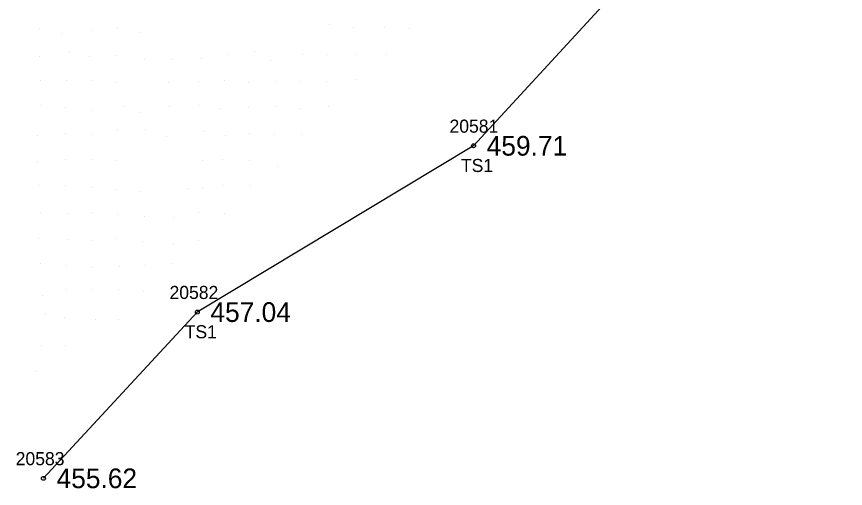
# Model space of a CAD drawing. Extents: x 1747760 to 1751131, y 649333 to 653784.
# Drawn here: x 1749176.7 to 1749239.9, y 651202.6 to 651238.6 of the extents above; entities that cross this region are included whole.
import ezdxf

# ---------------------------------------------------------------- set-up
doc = ezdxf.new("R2010")
doc.units = 0
for name, color, linetype in [('RD_DTM_BkLn2', 7, 'Continuous'), ('RD_DTM_BkLn_txCode', 7, 'Continuous'), ('RD_DTM_Spot', 7, 'Continuous'), ('RD_EX_TX_Misc_ELEV', 7, 'Continuous'), ('RD_SMD_Locator', 7, 'Continuous')]:
    doc.layers.add(name, color=color, linetype=linetype)

msp = doc.modelspace()

# ---------------------------------------------------------------- linework, layer by layer
at = {"layer": 'RD_DTM_BkLn2'}
msp.add_lwpolyline([(1749334.274, 651347.939), (1749311.737, 651326.42), (1749292.613, 651306.019), (1749271.131, 651290.935), (1749254.537, 651276.811), (1749242.73, 651265.483), (1749232.71, 651251.743), (1749211.561, 651228.743), (1749190.496, 651216.053), (1749178.766, 651203.369)], dxfattribs=at)
at = {"layer": 'RD_DTM_Spot'}
for p, q in [((1749178.471, 651237.712), (1749178.471, 651237.712)), ((1749182.48, 651237.556), (1749182.48, 651237.556)), ((1749184.386, 651237.715), (1749184.386, 651237.715)), ((1749200.569, 651237.99), (1749200.569, 651237.99)), ((1749202.383, 651237.788), (1749202.383, 651237.788)), ((1749204.76, 651237.744), (1749204.76, 651237.744)), ((1749206.691, 651237.729), (1749206.691, 651237.729)), ((1749180.152, 651237.316), (1749180.152, 651237.316)), ((1749186.198, 651237.38), (1749186.198, 651237.38)), ((1749178.46, 651235.542), (1749178.46, 651235.542)), ((1749180.761, 651235.896), (1749180.761, 651235.896)), ((1749182.305, 651235.564), (1749182.305, 651235.564)), ((1749184.269, 651235.663), (1749184.269, 651235.663)), ((1749192.763, 651235.694), (1749192.763, 651235.694)), ((1749194.883, 651235.919), (1749194.883, 651235.919)), ((1749198.549, 651235.71), (1749198.549, 651235.71)), ((1749200.429, 651235.678), (1749200.429, 651235.678)), ((1749202.625, 651235.729), (1749202.625, 651235.729)), ((1749204.905, 651235.748), (1749204.905, 651235.748)), ((1749186.464, 651235.362), (1749186.464, 651235.362)), ((1749188.527, 651235.349), (1749188.527, 651235.349)), ((1749190.836, 651235.437), (1749190.836, 651235.437)), ((1749196.039, 651235.231), (1749196.039, 651235.231)), ((1749178.572, 651233.712), (1749178.572, 651233.712)), ((1749180.534, 651233.7), (1749180.534, 651233.7)), ((1749182.414, 651233.722), (1749182.414, 651233.722)), ((1749190.572, 651233.656), (1749190.572, 651233.656)), ((1749192.597, 651233.73), (1749192.597, 651233.73)), ((1749198.351, 651233.683), (1749198.351, 651233.683)), ((1749200.384, 651233.662), (1749200.384, 651233.662)), ((1749202.613, 651233.824), (1749202.613, 651233.824)), ((1749184.292, 651233.566), (1749184.292, 651233.566)), ((1749188.33, 651233.538), (1749188.33, 651233.538)), ((1749194.39, 651233.537), (1749194.39, 651233.537)), ((1749196.454, 651233.613), (1749196.454, 651233.613)), ((1749178.516, 651231.823), (1749178.516, 651231.823)), ((1749188.405, 651231.747), (1749188.405, 651231.747)), ((1749190.652, 651231.793), (1749190.652, 651231.793)), ((1749196.519, 651231.74), (1749196.519, 651231.74)), ((1749180.416, 651231.63), (1749180.416, 651231.63)), ((1749182.466, 651231.474), (1749182.466, 651231.474)), ((1749184.845, 651231.729), (1749184.845, 651231.729)), ((1749186.144, 651231.318), (1749186.144, 651231.318)), ((1749192.209, 651231.617), (1749192.209, 651231.617)), ((1749194.394, 651231.695), (1749194.394, 651231.695)), ((1749198.362, 651231.619), (1749198.362, 651231.619)), ((1749200.5, 651231.724), (1749200.5, 651231.724)), ((1749184.417, 651229.943), (1749184.417, 651229.943)), ((1749186.577, 651230), (1749186.577, 651230)), ((1749191.02, 651229.871), (1749191.02, 651229.871)), ((1749178.29, 651229.562), (1749178.29, 651229.562)), ((1749180.477, 651229.69), (1749180.477, 651229.69)), ((1749182.432, 651229.637), (1749182.432, 651229.637)), ((1749188.119, 651229.48), (1749188.119, 651229.48)), ((1749192.68, 651229.517), (1749192.68, 651229.517)), ((1749194.513, 651229.697), (1749194.513, 651229.697)), ((1749196.386, 651229.594), (1749196.386, 651229.594)), ((1749198.425, 651229.632), (1749198.425, 651229.632)), ((1749178.32, 651227.499), (1749178.32, 651227.499)), ((1749180.476, 651227.69), (1749180.476, 651227.69)), ((1749182.404, 651227.687), (1749182.404, 651227.687)), ((1749184.286, 651227.597), (1749184.286, 651227.597)), ((1749190.896, 651227.585), (1749190.896, 651227.585)), ((1749192.436, 651227.712), (1749192.436, 651227.712)), ((1749194.491, 651227.635), (1749194.491, 651227.635)), ((1749196.634, 651227.14), (1749196.634, 651227.14)), ((1749178.488, 651225.722), (1749178.488, 651225.722)), ((1749180.469, 651225.695), (1749180.469, 651225.695)), ((1749182.505, 651225.597), (1749182.505, 651225.597)), ((1749184.222, 651225.42), (1749184.222, 651225.42)), ((1749189.783, 651225.5), (1749189.783, 651225.5)), ((1749190.925, 651225.474), (1749190.925, 651225.474)), ((1749192.481, 651225.683), (1749192.481, 651225.683)), ((1749194.585, 651225.699), (1749194.585, 651225.699)), ((1749186.154, 651225.222), (1749186.154, 651225.222)), ((1749178.522, 651223.647), (1749178.522, 651223.647)), ((1749180.687, 651223.556), (1749180.687, 651223.556)), ((1749182.432, 651223.654), (1749182.432, 651223.654)), ((1749190.555, 651223.648), (1749190.555, 651223.648)), ((1749192.55, 651223.585), (1749192.55, 651223.585)), ((1749184.42, 651223.503), (1749184.42, 651223.503)), ((1749186.438, 651223.337), (1749186.438, 651223.337)), ((1749188.717, 651223.237), (1749188.717, 651223.237)), ((1749178.355, 651221.684), (1749178.355, 651221.684)), ((1749184.363, 651221.637), (1749184.363, 651221.637)), ((1749180.602, 651221.609), (1749180.602, 651221.609)), ((1749182.504, 651221.524), (1749182.504, 651221.524)), ((1749186.279, 651221.435), (1749186.279, 651221.435)), ((1749188.705, 651221.287), (1749188.705, 651221.287)), ((1749190.612, 651221.534), (1749190.612, 651221.534)), ((1749178.561, 651219.752), (1749178.561, 651219.752)), ((1749188.574, 651219.773), (1749188.574, 651219.773)), ((1749180.509, 651219.587), (1749180.509, 651219.587)), ((1749182.402, 651219.425), (1749182.402, 651219.425)), ((1749184.53, 651219.55), (1749184.53, 651219.55)), ((1749186.471, 651219.645), (1749186.471, 651219.645)), ((1749178.691, 651217.324), (1749178.691, 651217.324)), ((1749180.556, 651217.762), (1749180.556, 651217.762)), ((1749182.528, 651217.8), (1749182.528, 651217.8)), ((1749184.519, 651217.741), (1749184.519, 651217.741)), ((1749186.406, 651217.643), (1749186.406, 651217.643)), ((1749178.94, 651215.858), (1749178.94, 651215.858)), ((1749180.385, 651215.672), (1749180.385, 651215.672)), ((1749182.698, 651215.504), (1749182.698, 651215.504)), ((1749184.485, 651215.516), (1749184.485, 651215.516)), ((1749178.648, 651213.485), (1749178.648, 651213.485)), ((1749180.439, 651213.507), (1749180.439, 651213.507)), ((1749178.265, 651211.539), (1749178.265, 651211.539))]:
    msp.add_line(p, q, dxfattribs=at)
at = {"layer": 'RD_SMD_Locator'}
for centre in [(1749211.561, 651228.743), (1749190.496, 651216.053), (1749178.766, 651203.369)]:
    msp.add_circle(centre, 0.15, dxfattribs=at)

# ---------------------------------------------------------------- texts
at = {"layer": 'RD_DTM_BkLn_txCode'}
for s, p in [('20581', (1749209.726, 651229.743)), ('TS1', (1749210.6, 651226.743)), ('20582', (1749188.378, 651217.053)), ('TS1', (1749189.535, 651214.053)), ('20583', (1749176.648, 651204.369))]:
    msp.add_text(s, height=1, dxfattribs=at).set_placement(p)
at = {"layer": 'RD_EX_TX_Misc_ELEV'}
for s, p in [('459.71', (1749212.561, 651227.993)), ('457.04', (1749191.496, 651215.303)), ('455.62', (1749179.766, 651202.619))]:
    msp.add_text(s, height=1.5, dxfattribs=at).set_placement(p)

doc.saveas('drawing.dxf')
